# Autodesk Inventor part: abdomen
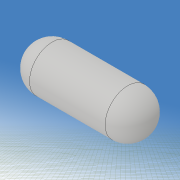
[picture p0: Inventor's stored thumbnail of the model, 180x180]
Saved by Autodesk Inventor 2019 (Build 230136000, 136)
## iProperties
Created: 2021-05
Part Number: abdomen
Material: 一般
Document SubType Name: Modeling
Designer: kikut
Density: 1 g/cm^3
Appearance: 既定
Author: kikut
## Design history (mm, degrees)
sketch "スケッチ5"
  geometry: L1 (-8, -5)-(-24, -5); L2 (-11, -8)-(-21, -8); L3 (4.924, 0)-(-29.546, 0) reference; L4 (0, -10.346)-(0, 1.724) reference; A1 r 3 centre (-11, -5) between (-11, -8) and (-8, -5); A2 r 3 centre (-21, -5) between (-24, -5) and (-21, -8); 1 further point
  constraints: 4 end point, 4 point on circle, 2 centre point, 1 horizontal
  dimensions: "d52" = 5 distance between parallel lines of L3 L1; "d53" = 3 radius of A1; "d54" = 3 radius of A2; "d55" = 0 distance from line of L1 A1.centre; "d56" = 0 distance from line of L1 A2.centre; "d57" = 10 distance of L2.start L2.end; "d58" = 90 deg dimension on A1.centre L2.start L1.start; "d59" = 90 deg dimension on A2.centre L1.end L2.end; "d60" = 8 distance from line of L1.start L4
revolve "回転2" sketch "スケッチ5" stored, may be unused: angle "d61" = 90 deg
node "ソリッド1"
